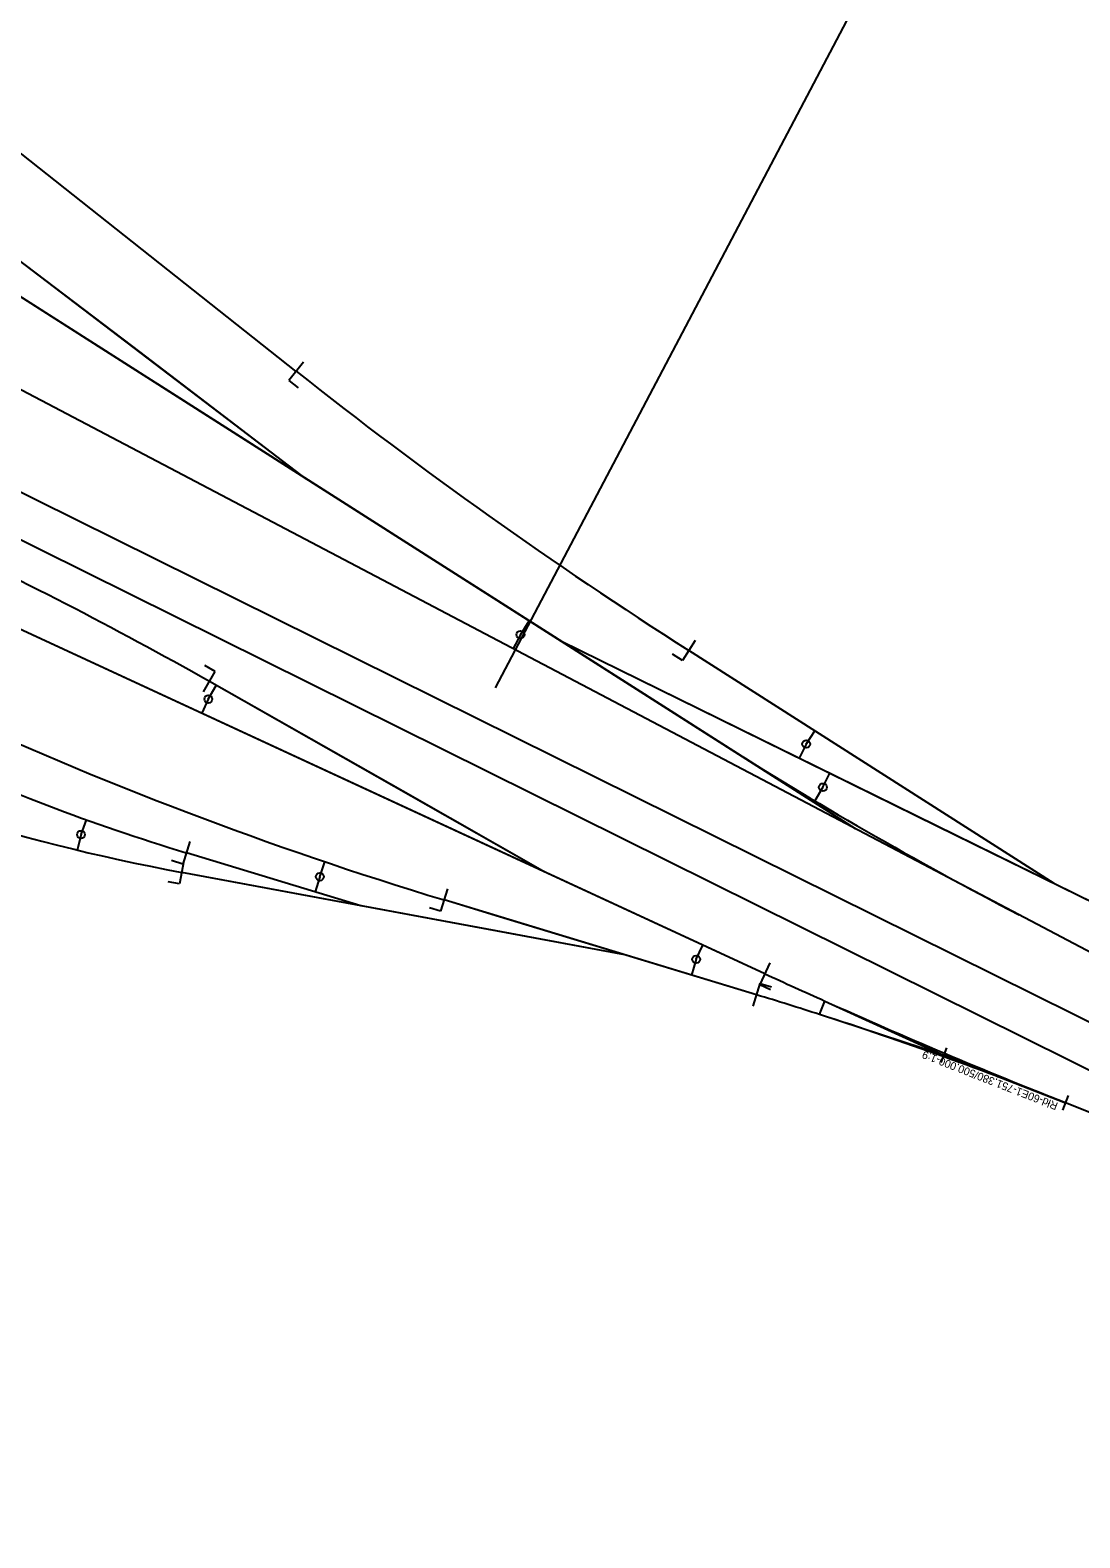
# Model space of a CAD drawing. Extents: x 6540402 to 6566579, y 5525343 to 5532423.
# Drawn here: x 6544801.8 to 6544935.2, y 5526087.8 to 5526279.6 of the extents above; entities that cross this region are included whole.
import ezdxf

# ---------------------------------------------------------------- set-up
doc = ezdxf.new("R2010")
doc.units = 0
for name, color, linetype in [('TOR_PS_OPIS_T-opisy dodatkowe', 7, 'Continuous'), ('TOR_PS_OPIS_T-symbole geometrii', 7, 'Continuous'), ('TOR_PS_OPIS_T-ukresy', 7, 'Continuous'), ('TOR_PS_T-rozjazdy projektowane', 7, 'Continuous'), ('TOR_PS_T-tory projektowane', 7, 'Continuous')]:
    doc.layers.add(name, color=color, linetype=linetype)

msp = doc.modelspace()

# ---------------------------------------------------------------- linework, layer by layer
at = {"layer": 'TOR_PS_OPIS_T-opisy dodatkowe'}
msp.add_line((6545207.83, 5526855.2), (6544860.89, 5526195.92), dxfattribs=at)
at = {"layer": 'TOR_PS_OPIS_T-symbole geometrii'}
for p, q in [((6544836.52, 5526237.36), (6544834.65, 5526235.01)), ((6544834.65, 5526235.01), (6544835.83, 5526234.08)), ((6544886.31, 5526201.92), (6544884.69, 5526199.39)), ((6544884.69, 5526199.39), (6544883.43, 5526200.2)), ((6544823.82, 5526195.4), (6544825.3, 5526198.01)), ((6544825.3, 5526198.01), (6544823.99, 5526198.75)), ((6544822.06, 5526176.38), (6544821.19, 5526173.51)), ((6544821.19, 5526173.51), (6544819.75, 5526173.94)), ((6544821.32, 5526173.92), (6544820.77, 5526170.97)), ((6544820.77, 5526170.97), (6544819.3, 5526171.25)), ((6544854.82, 5526170.37), (6544853.95, 5526167.5)), ((6544853.95, 5526167.5), (6544852.51, 5526167.94)), ((6544895.78, 5526160.92), (6544894.53, 5526158.19)), ((6544893.68, 5526155.43), (6544894.55, 5526158.3)), ((6544894.53, 5526158.19), (6544895.89, 5526157.56)), ((6544894.55, 5526158.3), (6544895.99, 5526157.87))]:
    msp.add_line(p, q, dxfattribs=at)
at = {"layer": 'TOR_PS_OPIS_T-ukresy'}
for p, q in [((6544864.09, 5526202.68), (6544865.21, 5526204.44)), ((6544864.09, 5526202.68), (6544863.15, 5526200.91)), ((6544824.41, 5526194.49), (6544825.39, 5526196.23)), ((6544824.41, 5526194.49), (6544823.57, 5526192.68)), ((6544900.42, 5526188.77), (6544901.5, 5526190.46)), ((6544900.42, 5526188.77), (6544899.54, 5526186.98)), ((6544902.54, 5526183.27), (6544903.42, 5526185.07)), ((6544902.54, 5526183.27), (6544901.51, 5526181.55)), ((6544808.23, 5526177.25), (6544808.91, 5526179.15)), ((6544808.23, 5526177.25), (6544807.75, 5526175.29)), ((6544838.59, 5526171.89), (6544839.24, 5526173.8)), ((6544838.59, 5526171.89), (6544838.01, 5526169.97)), ((6544886.43, 5526161.39), (6544887.27, 5526163.2)), ((6544886.43, 5526161.39), (6544885.82, 5526159.39))]:
    msp.add_line(p, q, dxfattribs=at)
for centre in [(6544864.09, 5526202.68), (6544824.41, 5526194.49), (6544900.42, 5526188.77), (6544902.54, 5526183.27), (6544808.23, 5526177.25), (6544838.59, 5526171.89), (6544886.43, 5526161.39)]:
    msp.add_circle(centre, 0.5, dxfattribs=at)
msp.add_arc((6545157.93, 5526610.79), 500, 237.4811, 242.5578, dxfattribs=at)
at = {"layer": 'TOR_PS_T-rozjazdy projektowane'}
for p, q in [((6544918.26, 5526150.12), (6544917.53, 5526148.26)), ((6544933.73, 5526144.07), (6544933, 5526142.21))]:
    msp.add_line(p, q, dxfattribs=at)
msp.add_lwpolyline([(6544902.77, 5526156.08), (6544917.89, 5526149.19), (6544933.37, 5526143.14), (6544917.89, 5526149.19), (6544902.1, 5526154.37)], close=True, dxfattribs=at)
at = {"layer": 'TOR_PS_T-tory projektowane'}
for p, q in [((6544530.07, 5526349.02), (6545286.66, 5525973.48)), ((6544530.07, 5526349.02), (6544972.13, 5526129.6)), ((6544906.68, 5526178), (6544644.93, 5526344.87)), ((6545001.28, 5526121.17), (6544572.92, 5526333.78)), ((6544906.68, 5526178), (6544668.75, 5526329.69)), ((6544888.27, 5526187.69), (6544644.63, 5526315.9)), ((6544906.68, 5526178), (6544703.82, 5526307.33)), ((6544836.91, 5526222.48), (6544731.76, 5526302.53)), ((6544906.68, 5526178), (6544716.98, 5526298.94)), ((6544836.91, 5526222.48), (6544736.68, 5526298.79)), ((6544835.58, 5526236.18), (6544761.72, 5526294.65)), ((6544895.16, 5526159.56), (6544607.34, 5526292.73)), ((6544848.33, 5526181.22), (6544610.61, 5526291.21)), ((6544906.68, 5526178), (6544752.05, 5526276.58)), ((6544810.94, 5526239.04), (6544752.05, 5526276.58)), ((6544836.91, 5526222.48), (6544769.77, 5526273.6)), ((6544836.91, 5526222.48), (6544781.7, 5526264.51)), ((6544814.8, 5526239.32), (6544781.7, 5526264.51)), ((6544810.94, 5526239.04), (6544775.87, 5526261.4)), ((6544906.68, 5526178), (6544810.94, 5526239.04)), ((6544854.45, 5526211.3), (6544810.94, 5526239.04)), ((6544819.38, 5526233.66), (6544810.94, 5526239.04)), ((6544836.91, 5526222.48), (6544814.8, 5526239.32)), ((6544820.37, 5526235.08), (6544814.8, 5526239.32)), ((6544836.91, 5526222.48), (6544820.37, 5526235.08)), ((6544854.45, 5526211.3), (6544819.38, 5526233.66)), ((6544906.68, 5526178), (6544854.45, 5526211.3)), ((6544860.35, 5526207.54), (6544854.45, 5526211.3)), ((6544906.68, 5526178), (6544860.35, 5526207.54)), ((6544883.24, 5526192.95), (6544860.35, 5526207.54)), ((6544869.23, 5526201.88), (6545008.53, 5526133.4)), ((6544869.23, 5526201.88), (6545078.07, 5526099.21)), ((6544869.23, 5526201.88), (6544884.14, 5526194.55)), ((6544931.95, 5526171.05), (6544885.5, 5526200.66)), ((6544867.2, 5526172.49), (6544824.56, 5526196.71)), ((6544849.12, 5526182.76), (6544824.56, 5526196.71)), ((6544884.14, 5526194.55), (6545078.07, 5526099.21)), ((6544884.14, 5526194.55), (6544917.04, 5526178.38)), ((6544906.68, 5526178), (6544883.24, 5526192.95)), ((6544889.14, 5526189.18), (6544883.24, 5526192.95)), ((6544925.08, 5526168.32), (6544888.27, 5526187.69)), ((6544906.68, 5526178), (6544889.14, 5526189.18)), ((6544867.2, 5526172.49), (6544849.12, 5526182.76)), ((6544895.16, 5526159.56), (6544848.33, 5526181.22)), ((6544886.08, 5526163.75), (6544848.33, 5526181.22)), ((6544917.04, 5526178.38), (6545078.07, 5526099.21)), ((6544917.04, 5526178.38), (6544941.39, 5526166.4)), ((6544843.79, 5526168.21), (6544821.62, 5526174.94)), ((6544827.89, 5526173.04), (6544821.62, 5526174.94)), ((6544877.35, 5526161.96), (6544821.05, 5526172.45)), ((6544827.45, 5526171.25), (6544821.05, 5526172.45)), ((6544843.79, 5526168.21), (6544827.89, 5526173.04)), ((6544854.13, 5526166.29), (6544827.45, 5526171.25)), ((6544894.12, 5526156.87), (6544854.38, 5526168.94)), ((6544861.45, 5526166.79), (6544854.38, 5526168.94)), ((6544894.12, 5526156.87), (6544861.45, 5526166.79)), ((6544887.42, 5526158.9), (6544861.45, 5526166.79)), ((6544938.35, 5526161.33), (6544925.08, 5526168.32)), ((6544861.02, 5526165), (6544854.13, 5526166.29)), ((6544877.35, 5526161.96), (6544861.02, 5526165)), ((6544895.16, 5526159.56), (6544886.08, 5526163.75)), ((6544894.12, 5526156.87), (6544887.42, 5526158.9)), ((6544990.93, 5526120.28), (6544933.37, 5526143.14)), ((6544939.87, 5526140.56), (6544933.37, 5526143.14))]:
    msp.add_line(p, q, dxfattribs=at)
for centre, radius, start, end in [((6545208.59, 5526707.43), 601, 231.63755, 237.48108), ((6544577.64, 5525761.93), 500, 60.4067, 65.1704), ((6544999.66, 5526647.36), 500, 245.1704, 253.1084), ((6544868.66, 5526428.05), 260, 245.1704, 259.4486), ((6544900.07, 5526433.29), 270, 245.1704, 253.1084), ((6545210.68, 5526841.48), 751.38, 245.17038, 245.80888), ((6544748.84, 5525678.44), 500, 72.1469, 73.1084), ((6545210.68, 5526841.48), 751.38, 245.80888, 248.34209), ((6544748.84, 5525678.44), 500, 68.3421, 72.1469)]:
    msp.add_arc(centre, radius, start, end, dxfattribs=at)

# ---------------------------------------------------------------- texts
at = {"layer": 'TOR_PS_T-rozjazdy projektowane'}
msp.add_text('Rłd-60E1-751,380/500,000-1:9', height=1, rotation=158.6522, dxfattribs=at).set_placement((6544932.51, 5526143.11))

doc.saveas('drawing.dxf')
